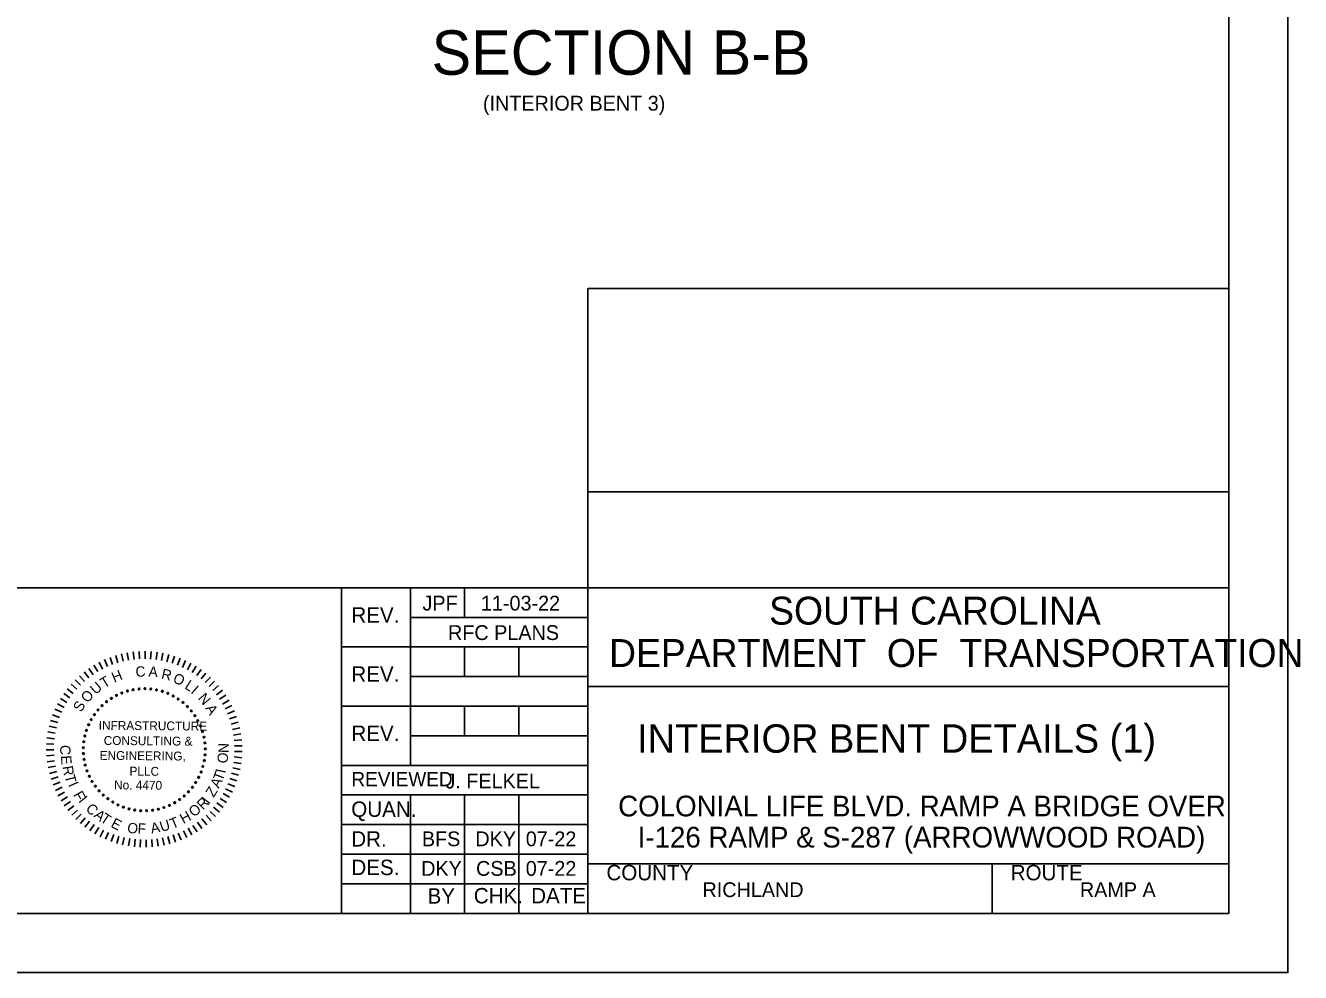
# Model space of a CAD drawing. Extents: x 1970675.2 to 1970711.3, y 796145.2 to 796167.2.
# Drawn here: x 1970700.57 to 1970711.34, y 796145.25 to 796153.25 of the extents above; entities that cross this region are included whole.
import ezdxf

# ---------------------------------------------------------------- set-up
doc = ezdxf.new("R2010")
doc.units = 0
for name, color, linetype in [('BR_BORDER LINES', 7, 'Continuous'), ('BR_TEXT', 7, 'Continuous'), ('Level 31', 7, 'Continuous')]:
    doc.layers.add(name, color=color, linetype=linetype)

msp = doc.modelspace()

# ---------------------------------------------------------------- linework, layer by layer
at = {"layer": 'BR_BORDER LINES'}
for p, q in [((1970710.736, 796145.746), (1970710.736, 796166.746)), ((1970705.319, 796145.746), (1970705.319, 796151.023)), ((1970705.319, 796151.023), (1970710.736, 796151.023)), ((1970705.319, 796149.308), (1970710.736, 796149.308)), ((1970697.87, 796148.496), (1970703.236, 796148.496)), ((1970703.236, 796145.746), (1970703.236, 796148.496)), ((1970703.236, 796148.496), (1970710.736, 796148.496)), ((1970703.819, 796148.496), (1970703.819, 796146.996)), ((1970704.277, 796148.246), (1970704.277, 796148.496)), ((1970703.819, 796148.246), (1970705.319, 796148.246)), ((1970703.236, 796147.996), (1970705.319, 796147.996)), ((1970704.277, 796147.746), (1970704.277, 796147.996)), ((1970704.736, 796147.746), (1970704.736, 796147.996)), ((1970703.819, 796147.746), (1970705.319, 796147.746)), ((1970705.319, 796147.663), (1970705.319, 796147.663)), ((1970705.319, 796147.663), (1970710.736, 796147.663)), ((1970703.236, 796147.496), (1970705.319, 796147.496)), ((1970704.277, 796147.246), (1970704.277, 796147.496)), ((1970704.736, 796147.246), (1970704.736, 796147.496)), ((1970703.819, 796147.246), (1970705.319, 796147.246)), ((1970703.236, 796146.996), (1970705.319, 796146.996)), ((1970703.236, 796146.746), (1970705.319, 796146.746)), ((1970703.819, 796146.746), (1970703.819, 796145.746)), ((1970704.277, 796146.746), (1970704.277, 796145.746)), ((1970704.736, 796146.746), (1970704.736, 796145.746)), ((1970703.236, 796146.496), (1970705.319, 796146.496)), ((1970703.236, 796146.246), (1970705.319, 796146.246)), ((1970705.319, 796146.163), (1970710.736, 796146.163)), ((1970705.417, 796146.163), (1970710.736, 796146.163)), ((1970708.736, 796145.746), (1970708.736, 796146.163)), ((1970703.236, 796145.996), (1970705.319, 796145.996)), ((1970677.07, 796145.746), (1970710.736, 796145.746))]:
    msp.add_line(p, q, dxfattribs=at)
at = {"layer": 'BR_TEXT'}
for p, q in [((1970701.233, 796147.889), (1970701.259, 796147.83)), ((1970701.28, 796147.908), (1970701.302, 796147.848)), ((1970701.328, 796147.924), (1970701.347, 796147.863)), ((1970701.377, 796147.937), (1970701.392, 796147.875)), ((1970701.426, 796147.947), (1970701.437, 796147.885)), ((1970701.476, 796147.955), (1970701.483, 796147.891)), ((1970701.526, 796147.959), (1970701.53, 796147.895)), ((1970701.577, 796147.96), (1970701.576, 796147.896)), ((1970701.627, 796147.958), (1970701.623, 796147.894)), ((1970701.678, 796147.953), (1970701.669, 796147.889)), ((1970701.727, 796147.944), (1970701.715, 796147.882)), ((1970701.777, 796147.933), (1970701.761, 796147.872)), ((1970701.825, 796147.919), (1970701.806, 796147.859)), ((1970701.873, 796147.902), (1970701.849, 796147.843)), ((1970701.061, 796147.785), (1970701.1, 796147.735)), ((1970701.101, 796147.815), (1970701.137, 796147.762)), ((1970701.144, 796147.842), (1970701.177, 796147.788)), ((1970701.188, 796147.867), (1970701.217, 796147.81)), ((1970701.919, 796147.882), (1970701.892, 796147.824)), ((1970701.964, 796147.859), (1970701.934, 796147.803)), ((1970702.008, 796147.834), (1970701.974, 796147.78)), ((1970702.05, 796147.806), (1970702.013, 796147.754)), ((1970700.95, 796147.682), (1970700.998, 796147.639)), ((1970700.985, 796147.718), (1970701.03, 796147.673)), ((1970701.022, 796147.753), (1970701.064, 796147.705)), ((1970702.09, 796147.775), (1970702.05, 796147.726)), ((1970702.128, 796147.742), (1970702.085, 796147.695)), ((1970702.164, 796147.707), (1970702.119, 796147.663)), ((1970700.888, 796147.602), (1970700.94, 796147.566)), ((1970700.918, 796147.643), (1970700.968, 796147.604)), ((1970702.198, 796147.67), (1970702.15, 796147.628)), ((1970702.23, 796147.631), (1970702.179, 796147.592)), ((1970702.259, 796147.589), (1970702.206, 796147.554)), ((1970700.814, 796147.47), (1970700.872, 796147.445)), ((1970700.836, 796147.516), (1970700.892, 796147.486)), ((1970700.861, 796147.56), (1970700.915, 796147.527)), ((1970702.286, 796147.546), (1970702.231, 796147.514)), ((1970702.31, 796147.502), (1970702.253, 796147.473)), ((1970700.778, 796147.376), (1970700.839, 796147.357)), ((1970700.795, 796147.424), (1970700.854, 796147.401)), ((1970702.331, 796147.456), (1970702.272, 796147.431)), ((1970702.349, 796147.409), (1970702.289, 796147.388)), ((1970702.364, 796147.361), (1970702.303, 796147.343)), ((1970700.754, 796147.278), (1970700.817, 796147.267)), ((1970700.765, 796147.327), (1970700.827, 796147.312)), ((1970702.377, 796147.312), (1970702.315, 796147.298)), ((1970702.386, 796147.263), (1970702.324, 796147.252)), ((1970700.743, 796147.178), (1970700.806, 796147.174)), ((1970700.747, 796147.228), (1970700.81, 796147.221)), ((1970702.393, 796147.212), (1970702.33, 796147.206)), ((1970702.396, 796147.162), (1970702.333, 796147.16)), ((1970700.741, 796147.127), (1970700.805, 796147.128)), ((1970700.743, 796147.077), (1970700.807, 796147.081)), ((1970700.748, 796147.027), (1970700.811, 796147.035)), ((1970702.394, 796147.061), (1970702.33, 796147.067)), ((1970702.397, 796147.112), (1970702.333, 796147.113)), ((1970700.756, 796146.977), (1970700.819, 796146.989)), ((1970700.767, 796146.927), (1970700.829, 796146.943)), ((1970702.367, 796146.912), (1970702.306, 796146.929)), ((1970702.379, 796146.961), (1970702.317, 796146.974)), ((1970702.388, 796147.011), (1970702.325, 796147.02)), ((1970700.781, 796146.879), (1970700.842, 796146.898)), ((1970700.798, 796146.831), (1970700.857, 796146.855)), ((1970700.818, 796146.785), (1970700.875, 796146.812)), ((1970702.334, 796146.817), (1970702.276, 796146.841)), ((1970702.352, 796146.864), (1970702.292, 796146.885)), ((1970700.84, 796146.74), (1970700.896, 796146.77)), ((1970700.866, 796146.696), (1970700.92, 796146.73)), ((1970702.264, 796146.683), (1970702.211, 796146.717)), ((1970702.29, 796146.726), (1970702.235, 796146.757)), ((1970702.314, 796146.771), (1970702.256, 796146.798)), ((1970700.893, 796146.654), (1970700.945, 796146.691)), ((1970700.924, 796146.614), (1970700.973, 796146.654)), ((1970700.957, 796146.575), (1970701.004, 796146.618)), ((1970702.171, 796146.564), (1970702.125, 796146.607)), ((1970702.204, 796146.602), (1970702.155, 796146.642)), ((1970702.236, 796146.641), (1970702.184, 796146.679)), ((1970700.992, 796146.539), (1970701.036, 796146.585)), ((1970701.029, 796146.505), (1970701.07, 796146.553)), ((1970701.068, 796146.473), (1970701.107, 796146.524)), ((1970701.109, 796146.444), (1970701.145, 796146.497)), ((1970702.016, 796146.435), (1970701.981, 796146.489)), ((1970702.057, 796146.464), (1970702.02, 796146.515)), ((1970702.097, 796146.495), (1970702.057, 796146.544)), ((1970702.135, 796146.528), (1970702.092, 796146.575)), ((1970701.152, 796146.417), (1970701.184, 796146.472)), ((1970701.196, 796146.393), (1970701.225, 796146.45)), ((1970701.242, 796146.372), (1970701.267, 796146.43)), ((1970701.289, 796146.353), (1970701.311, 796146.413)), ((1970701.337, 796146.337), (1970701.355, 796146.399)), ((1970701.386, 796146.325), (1970701.4, 796146.387)), ((1970701.737, 796146.322), (1970701.724, 796146.384)), ((1970701.786, 796146.333), (1970701.769, 796146.395)), ((1970701.834, 796146.348), (1970701.814, 796146.408)), ((1970701.881, 796146.366), (1970701.857, 796146.424)), ((1970701.928, 796146.386), (1970701.9, 796146.443)), ((1970701.972, 796146.409), (1970701.941, 796146.465)), ((1970701.436, 796146.315), (1970701.446, 796146.378)), ((1970701.486, 796146.309), (1970701.492, 796146.372)), ((1970701.536, 796146.305), (1970701.538, 796146.369)), ((1970701.586, 796146.305), (1970701.585, 796146.368)), ((1970701.637, 796146.307), (1970701.632, 796146.371)), ((1970701.687, 796146.313), (1970701.678, 796146.376))]:
    msp.add_line(p, q, dxfattribs=at)
for centre, start, end in [((1970701.291, 796147.562), 32.7576, 212.7576), ((1970701.291, 796147.562), 212.7576, 32.7576), ((1970701.334, 796147.587), 27.2191, 207.2191), ((1970701.334, 796147.587), 207.2191, 27.2191), ((1970701.38, 796147.607), 21.6807, 201.6807), ((1970701.38, 796147.607), 201.6807, 21.6807), ((1970701.427, 796147.624), 16.1422, 196.1422), ((1970701.427, 796147.624), 196.1422, 16.1422), ((1970701.475, 796147.635), 10.6038, 190.6038), ((1970701.475, 796147.635), 190.6038, 10.6038), ((1970701.525, 796147.642), 5.0653, 185.0653), ((1970701.525, 796147.642), 185.0653, 5.0653), ((1970701.575, 796147.644), 359.5268, 179.5268), ((1970701.575, 796147.644), 179.5268, 359.5268), ((1970701.624, 796147.641), 353.9884, 173.9884), ((1970701.624, 796147.641), 173.9884, 353.9884), ((1970701.673, 796147.633), 168.4499, 348.4499), ((1970701.673, 796147.633), 348.4499, 168.4499), ((1970701.722, 796147.621), 342.9114, 162.9114), ((1970701.722, 796147.621), 162.9114, 342.9114), ((1970701.769, 796147.604), 337.373, 157.373), ((1970701.769, 796147.604), 157.373, 337.373), ((1970701.814, 796147.582), 331.8345, 151.8345), ((1970701.814, 796147.582), 151.8345, 331.8345), ((1970701.178, 796147.464), 49.373, 229.373), ((1970701.178, 796147.464), 229.373, 49.373), ((1970701.213, 796147.501), 43.8345, 223.8345), ((1970701.213, 796147.501), 223.8345, 43.8345), ((1970701.25, 796147.533), 38.2961, 218.2961), ((1970701.25, 796147.533), 218.2961, 38.2961), ((1970701.856, 796147.556), 146.2961, 326.2961), ((1970701.856, 796147.556), 326.2961, 146.2961), ((1970701.896, 796147.527), 140.7576, 320.7576), ((1970701.896, 796147.527), 320.7576, 140.7576), ((1970701.933, 796147.493), 135.2191, 315.2191), ((1970701.933, 796147.493), 315.2191, 135.2191), ((1970701.967, 796147.456), 129.6807, 309.6807), ((1970701.967, 796147.456), 309.6807, 129.6807), ((1970701.121, 796147.383), 60.4499, 240.4499), ((1970701.121, 796147.383), 240.4499, 60.4499), ((1970701.148, 796147.425), 54.9114, 234.9114), ((1970701.148, 796147.425), 234.9114, 54.9114), ((1970701.997, 796147.416), 124.1422, 304.1422), ((1970701.997, 796147.416), 304.1422, 124.1422), ((1970702.022, 796147.374), 118.6038, 298.6038), ((1970702.022, 796147.374), 298.6038, 118.6038), ((1970701.067, 796147.244), 77.0653, 257.0653), ((1970701.067, 796147.244), 257.0653, 77.0653), ((1970701.08, 796147.292), 71.5268, 251.5268), ((1970701.08, 796147.292), 251.5268, 71.5268), ((1970701.099, 796147.339), 65.9884, 245.9884), ((1970701.099, 796147.339), 245.9884, 65.9884), ((1970702.044, 796147.329), 113.0653, 293.0653), ((1970702.044, 796147.329), 293.0653, 113.0653), ((1970702.061, 796147.282), 107.5268, 287.5268), ((1970702.061, 796147.282), 287.5268, 107.5268), ((1970701.054, 796147.146), 88.1422, 268.1422), ((1970701.058, 796147.195), 82.6038, 262.6038), ((1970701.054, 796147.146), 268.1422, 88.1422), ((1970701.058, 796147.195), 262.6038, 82.6038), ((1970702.074, 796147.234), 101.9884, 281.9884), ((1970702.074, 796147.234), 281.9884, 101.9884), ((1970702.082, 796147.185), 96.4499, 276.4499), ((1970702.085, 796147.135), 90.9114, 270.9114), ((1970702.082, 796147.185), 276.4499, 96.4499), ((1970702.085, 796147.135), 270.9114, 90.9114), ((1970701.055, 796147.096), 93.6807, 273.6807), ((1970701.06, 796147.046), 99.2191, 279.2191), ((1970701.055, 796147.096), 273.6807, 93.6807), ((1970701.06, 796147.046), 279.2191, 99.2191), ((1970702.077, 796147.036), 79.8345, 259.8345), ((1970702.077, 796147.036), 259.8345, 79.8345), ((1970702.083, 796147.085), 85.373, 265.373), ((1970702.083, 796147.085), 265.373, 85.373), ((1970701.07, 796146.998), 104.7576, 284.7576), ((1970701.07, 796146.998), 284.7576, 104.7576), ((1970701.085, 796146.95), 110.2961, 290.2961), ((1970701.085, 796146.95), 290.2961, 110.2961), ((1970702.05, 796146.94), 68.7576, 248.7576), ((1970702.05, 796146.94), 248.7576, 68.7576), ((1970702.065, 796146.987), 74.2961, 254.2961), ((1970702.065, 796146.987), 254.2961, 74.2961), ((1970701.105, 796146.904), 115.8345, 295.8345), ((1970701.105, 796146.904), 295.8345, 115.8345), ((1970701.128, 796146.86), 121.373, 301.373), ((1970701.128, 796146.86), 301.373, 121.373), ((1970701.156, 796146.819), 126.9114, 306.9114), ((1970701.156, 796146.819), 306.9114, 126.9114), ((1970701.976, 796146.811), 52.1422, 232.1422), ((1970701.976, 796146.811), 232.1422, 52.1422), ((1970702.004, 796146.851), 57.6807, 237.6807), ((1970702.004, 796146.851), 237.6807, 57.6807), ((1970702.029, 796146.895), 63.2191, 243.2191), ((1970702.029, 796146.895), 243.2191, 63.2191), ((1970701.188, 796146.781), 132.4499, 312.4499), ((1970701.188, 796146.781), 312.4499, 132.4499), ((1970701.223, 796146.745), 137.9884, 317.9884), ((1970701.223, 796146.745), 317.9884, 137.9884), ((1970701.262, 796146.714), 143.5268, 323.5268), ((1970701.262, 796146.714), 323.5268, 143.5268), ((1970701.868, 796146.708), 35.5268, 215.5268), ((1970701.868, 796146.708), 215.5268, 35.5268), ((1970701.907, 796146.738), 41.0653, 221.0653), ((1970701.907, 796146.738), 221.0653, 41.0653), ((1970701.943, 796146.773), 46.6038, 226.6038), ((1970701.943, 796146.773), 226.6038, 46.6038), ((1970701.303, 796146.686), 149.0653, 329.0653), ((1970701.303, 796146.686), 329.0653, 149.0653), ((1970701.347, 796146.662), 154.6038, 334.6038), ((1970701.347, 796146.662), 334.6038, 154.6038), ((1970701.393, 796146.643), 340.1422, 160.1422), ((1970701.393, 796146.643), 160.1422, 340.1422), ((1970701.441, 796146.628), 345.6807, 165.6807), ((1970701.441, 796146.628), 165.6807, 345.6807), ((1970701.489, 796146.618), 171.2191, 351.2191), ((1970701.489, 796146.618), 351.2191, 171.2191), ((1970701.539, 796146.613), 356.7576, 176.7576), ((1970701.539, 796146.613), 176.7576, 356.7576), ((1970701.589, 796146.613), 2.2961, 182.2961), ((1970701.589, 796146.613), 182.2961, 2.2961), ((1970701.639, 796146.617), 7.8345, 187.8345), ((1970701.639, 796146.617), 187.8345, 7.8345), ((1970701.688, 796146.626), 13.373, 193.373), ((1970701.688, 796146.626), 193.373, 13.373), ((1970701.735, 796146.64), 18.9114, 198.9114), ((1970701.735, 796146.64), 198.9114, 18.9114), ((1970701.782, 796146.658), 24.4499, 204.4499), ((1970701.782, 796146.658), 204.4499, 24.4499), ((1970701.826, 796146.681), 29.9884, 209.9884), ((1970701.826, 796146.681), 209.9884, 29.9884)]:
    msp.add_arc(centre, 0.00701, start, end, dxfattribs=at)
at = {"layer": 'Level 31'}
msp.add_line((1970708.028, 796147.223), (1970708.028, 796147.223), dxfattribs=at)
msp.add_lwpolyline([(1970675.236, 796167.246), (1970675.236, 796145.246), (1970711.236, 796145.246), (1970711.236, 796167.246)], dxfattribs=at)

# ---------------------------------------------------------------- texts
at = {"layer": 'BR_TEXT'}
for s, height, p in [('SECTION B-B', 0.375, (1970703.998, 796152.83)), ('JPF', 0.125, (1970703.921, 796148.304)), ('11-03-22', 0.125, (1970704.415, 796148.304)), ('REV.', 0.13, (1970703.32, 796148.202)), ('SOUTH CAROLINA', 0.23587, (1970706.851, 796148.185)), ('RFC PLANS', 0.125, (1970704.137, 796148.055)), ('DEPARTMENT  OF  TRANSPORTATION', 0.23587, (1970705.498, 796147.827)), ('REV.', 0.13, (1970703.32, 796147.702)), ('INTERIOR BENT DETAILS (1)', 0.24, (1970705.735, 796147.103)), ('REV.', 0.13, (1970703.32, 796147.202)), ('REVIEWED', 0.12, (1970703.32, 796146.82)), ('J. FELKEL', 0.125, (1970704.115, 796146.801)), ('COLONIAL LIFE BLVD. RAMP A BRIDGE OVER', 0.175, (1970705.575, 796146.565)), ('QUAN.', 0.13, (1970703.319, 796146.561)), ('DR.', 0.13, (1970703.319, 796146.31)), ('BFS', 0.125, (1970703.916, 796146.313)), ('DKY', 0.125, (1970704.368, 796146.313)), ('07-22', 0.125, (1970704.794, 796146.313)), ('I-126 RAMP & S-287 (ARROWWOOD ROAD)', 0.175, (1970705.74, 796146.302)), ('DES.', 0.13, (1970703.32, 796146.069)), ('DKY', 0.125, (1970703.91, 796146.063)), ('CSB', 0.125, (1970704.374, 796146.063)), ('07-22', 0.125, (1970704.794, 796146.063)), ('COUNTY', 0.13, (1970705.476, 796146.025)), ('ROUTE', 0.13, (1970708.893, 796146.025)), ('BY', 0.13, (1970703.964, 796145.828)), ('CHK.', 0.13, (1970704.355, 796145.83)), ('DATE', 0.13, (1970704.84, 796145.83)), ('RICHLAND', 0.125, (1970706.288, 796145.883)), ('RAMP A', 0.125, (1970709.478, 796145.883))]:
    msp.add_text(s, height=height, dxfattribs=at).set_placement(p)
for s, height, rotation, p in [('(INTERIOR BENT 3)', 0.125, 360, (1970704.432, 796152.527)), ('H', 0.0872, 22.7882, (1970701.316, 796147.693)), ('C', 0.0872, 4.7281, (1970701.499, 796147.742)), ('A', 0.0872, 355.6981, (1970701.603, 796147.747)), ('R', 0.0872, 346.6681, (1970701.708, 796147.73)), ('U', 0.0872, 40.8482, (1970701.158, 796147.589)), ('T', 0.0872, 31.8182, (1970701.231, 796147.645)), ('O', 0.0872, 337.638, (1970701.805, 796147.7)), ('L', 0.0872, 327.108, (1970701.904, 796147.65)), ('O', 0.0872, 49.8782, (1970701.091, 796147.518)), ('I', 0.0872, 319.578, (1970701.957, 796147.612)), ('N', 0.0872, 310.548, (1970702.018, 796147.561)), ('S', 0.0872, 58.9083, (1970701.036, 796147.44)), ('A', 0.0872, 301.5179, (1970702.083, 796147.479)), ('INFRASTRUCTURE', 0.07477, 359.5268, (1970701.184, 796147.297)), ('CONSULTING &', 0.07477, 359.5268, (1970701.226, 796147.169)), ('C', 0.0872, 267.025, (1970700.861, 796147.17)), ('N', 0.0872, 89.2085, (1970702.282, 796147.1)), ('E', 0.0872, 273.025, (1970700.865, 796147.078)), ('ENGINEERING,', 0.07477, 359.5268, (1970701.192, 796147.043)), ('O', 0.0872, 83.2085, (1970702.271, 796147.009)), ('R', 0.0872, 279.025, (1970700.878, 796146.986)), ('T', 0.0872, 285.025, (1970700.895, 796146.907)), ('PLLC', 0.0748, 359.5268, (1970701.444, 796146.91)), ('T', 0.0872, 69.3954, (1970702.23, 796146.857)), ('I', 0.0872, 77.9093, (1970702.255, 796146.924)), ('I', 0.0872, 293.7713, (1970700.925, 796146.834)), ('No. 4470', 0.0748, 359.5268, (1970701.314, 796146.793)), ('Z', 0.0872, 57.3954, (1970702.155, 796146.72)), ('A', 0.0872, 63.3954, (1970702.199, 796146.797)), ('F', 0.0872, 299.7713, (1970700.966, 796146.748)), ('I', 0.0872, 308.5268, (1970701.008, 796146.694)), ('R', 0.0872, 44.5268, (1970702.065, 796146.615)), ('I', 0.0872, 52.3339, (1970702.114, 796146.662)), ('C', 0.0872, 314.5268, (1970701.068, 796146.624)), ('A', 0.0872, 320.5268, (1970701.137, 796146.565)), ('T', 0.0872, 326.5268, (1970701.191, 796146.527)), ('H', 0.0872, 28.5268, (1970701.9, 796146.499)), ('O', 0.0872, 38.5268, (1970701.988, 796146.555)), ('E', 0.0872, 332.5268, (1970701.28, 796146.479)), ('O', 0.0872, 350.5268, (1970701.42, 796146.43)), ('F', 0.0872, 356.5268, (1970701.511, 796146.421)), ('A', 0.0872, 10.5268, (1970701.631, 796146.42)), ('U', 0.0872, 16.5268, (1970701.715, 796146.433)), ('T', 0.0872, 22.5268, (1970701.807, 796146.457))]:
    msp.add_text(s, height=height, rotation=rotation, dxfattribs=at).set_placement(p)

doc.saveas('drawing.dxf')
